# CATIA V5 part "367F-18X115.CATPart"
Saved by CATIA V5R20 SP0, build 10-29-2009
Part number: 367F-18X115
Definition: NONE
Nomenclature: 367F-18X115
Source: Unknown
Description: 367F-18X115
Bounding box of the stored display mesh (mm): x 0 to 115, y -14 to 14, z -14 to 14
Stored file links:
  C:\Users\Utente\Desktop\IO LAVORO\3D X SITO CF\X SITO\PLASTICA\3D files 367\367F-18X115.CATPart
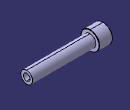
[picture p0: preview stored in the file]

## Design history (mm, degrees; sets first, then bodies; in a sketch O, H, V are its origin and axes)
Body1 "367F-18X115" (main body)
  Solid1: solid without history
